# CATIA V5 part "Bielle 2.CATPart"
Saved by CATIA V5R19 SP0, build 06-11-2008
Part number: Bielle 2
Bounding box of the stored display mesh (mm): x -5 to 5, y -9.993 to 129.996, z -9.993 to 90
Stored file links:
  D:\thinkmotion-MPB\CIAO82010_JCF\PLANTECOSTE\0593\assemblage 593\Bielle 2.CATPart
  D:\thinkmotion-MPB\CIAO82010_JCF\PLANTECOSTE\0593\assemblage 593\593-Plantecoste.CATProduct
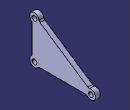
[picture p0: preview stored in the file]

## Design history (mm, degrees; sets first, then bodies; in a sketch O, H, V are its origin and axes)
External parameters (linked from other documents)
  `External.Diamètre axe` = 10 mm
  External.Longueur.1 = 300 mm
Body1 (main body)
  Sketch1 on yz-plane, origin (0, 0, 0), H (0, 1, 0), V (0, 0, 1)
    circle A1 centre (0, 0) radius 5
    circle A2 centre (0, 80) radius 5
    point P1 (0, 80)
    point P2 (0, 75)
    circle A3 centre (120, 0) radius 5
    point P3 (120, 0)
    construction line L1 (0, 0) -> (120, 0)
    construction line L2 (0, 0) -> (0, 80)
    point P5 (-5, 71.3397)
    line L3 (9.9793, 79.3564) -> (115.5677, 8.9641)
    point P7 (9.9793, 79.3564)
    arc A4 centre (0, 0) radius 10 from (-5, 8.6603) to (8.6603, -5) ccw
    arc A5 centre (120, 0) radius 10 from (111.3397, -5) to (115.5677, 8.9641) ccw
    arc A6 centre (0, 80) radius 10 from (9.9793, 79.3564) to (-5, 71.3397) ccw
    point P10 (9.9793, 79.3564)
    line L4 (-5, 8.6603) -> (-5, 71.3397)
    line L5 (111.3397, -5) -> (8.6603, -5)
    axis line L6 (120, 0) -> (0, 80)
    radius A1 = 5 {= `External.Diamètre axe` /2}
    radius A2 = 5 {= `External.Diamètre axe` /2}
    radius A3 = 5 {= `External.Diamètre axe` /2}
    radius A6 = 10 {= `External.Diamètre axe`}
    radius A5 = 10 {= `External.Diamètre axe`}
    distance P5 L2 = 5 {= `External.Diamètre axe` /2}
    distance L5 L1 = 5 {= `External.Diamètre axe` /2}
    radius A4 = 10 {= `External.Diamètre axe`}
    distance L1 P1 = 80 {= External.Longueur.1 /3.75}
    distance P3 L2 = 120 {= External.Longueur.1 /2.5}
    distance L6 L3 = 5 {= `External.Diamètre axe` /2}
    coincidence: P1 V, A2 P2, P2 V, P3 H, P10 P7
    horizontal: L1 H, L5 H
    vertical: L2 V, L4 V
  Pad1: profile Sketch1, direction (1, 0, 0), length 5, opposite side length 5
  Fillet1: radius 5 {= `External.Diamètre axe` /2}, on edge [face of Pad1 from Sketch1.A6 | face of Pad1 from Sketch1.L3]; edge [face of Pad1 from Sketch1.L4 | face of Pad1 from Sketch1.A6]; edge [face of Pad1 from Sketch1.A4 | face of Pad1 from Sketch1.L4]; edge [face of Pad1 from Sketch1.L5 | face of Pad1 from Sketch1.A4]; edge [face of Pad1 from Sketch1.A5 | face of Pad1 from Sketch1.L5]; edge [face of Pad1 from Sketch1.L3 | face of Pad1 from Sketch1.A5]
